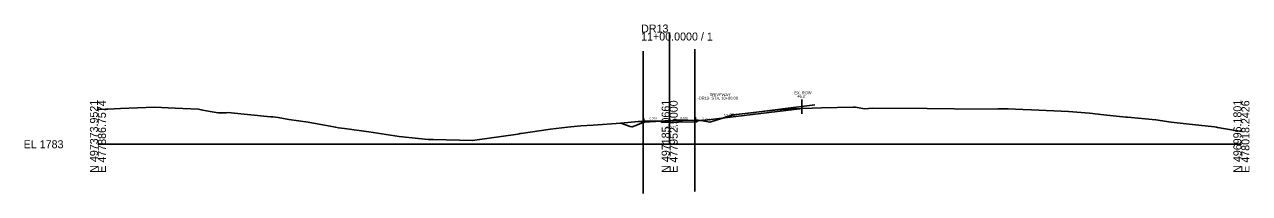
# Model space of a CAD drawing. Extents: x -26 to 403, y -10 to 2160.
# Drawn here: x -25.7 to 402.8, y 982.7 to 1042.1 of the extents above; entities that cross this region are included whole.
import ezdxf

# ---------------------------------------------------------------- set-up
doc = ezdxf.new("R2010")
doc.units = 0
for name, color, linetype in [('Exist Cross Section Cell', 7, 'Continuous'), ('Exist XS Center Line Elevation Label', 7, 'Continuous'), ('Exist XS Ground Line', 7, 'Continuous'), ('Pattern 3', 7, 'Continuous'), ('Prop XS Ditch Slope Text', 7, 'Continuous'), ('Prop XS Earthwork Shape', 7, 'Continuous'), ('Prop XS EOT Tick Mark', 7, 'Continuous'), ('Prop XS Finish Grade', 7, 'Continuous'), ('Prop XS Finish Grade Earthwork', 7, 'Continuous'), ('Prop XS Finish Grade Pavement', 7, 'Continuous'), ('Prop XS Pvmt Edge Slope', 7, 'Continuous'), ('Prop XS SE Text', 7, 'Continuous'), ('Prop XS Shoulder Borrow Shape', 7, 'Continuous'), ('Prop XS Subgrade Earthwork', 7, 'Continuous'), ('Scratch_Level_1', 7, 'Continuous'), ('Scratch_Level_4', 7, 'Continuous'), ('Scratch_Level_5', 7, 'Continuous'), ('Scratch_Level_6', 7, 'Continuous')]:
    doc.layers.add(name, color=color, linetype=linetype)

msp = doc.modelspace()

# ---------------------------------------------------------------- linework, layer by layer
at = {"layer": 'Exist Cross Section Cell'}
for p, q in [((200, 1000), (200, 1039.21)), ((0, 1000), (200, 1000)), ((200, 1000), (400, 1000))]:
    msp.add_line(p, q, dxfattribs=at)
at = {"layer": 'Exist XS Ground Line'}
msp.add_lwpolyline([(0, 1012.22), (2.69, 1012.35), (3.42, 1012.37), (7.84, 1012.53), (19.84, 1012.97), (27.02, 1012.64), (35.13, 1012.29), (36.66, 1011.95), (39.2, 1011.5), (42.1, 1010.99), (42.46, 1011), (42.89, 1011.02), (43.28, 1011.03), (43.98, 1011.05), (44.3, 1011.06), (44.83, 1011.08), (45.44, 1011.09), (60.37, 1009.6), (61.15, 1009.6), (63, 1009.4), (66.82, 1008.73), (73.59, 1007.75), (83.06, 1005.98), (84.18, 1005.79), (86.28, 1005.48), (94.77, 1004.34), (99.3, 1003.63), (105.36, 1002.75), (115.55, 1001.69), (115.95, 1001.65), (117.25, 1001.63), (131.07, 1001.37), (146.9, 1003.6), (147.39, 1003.67), (147.72, 1003.72), (148.04, 1003.76), (158.31, 1005.24), (164.28, 1005.97), (168.9, 1006.42), (173.26, 1006.73), (182.88, 1007.41), (186.23, 1006.29), (186.84, 1006.07), (187.76, 1006.46), (189.89, 1007.33), (190.76, 1007.69), (191.98, 1007.87), (192.39, 1007.89), (194.62, 1008.02), (196.46, 1008.08), (197.27, 1008.11), (198.27, 1008.17), (198.77, 1008.2), (199.97, 1008.27), (200.75, 1008.31), (202.53, 1008.41), (204.54, 1008.41), (205.16, 1008.42), (205.46, 1008.42), (206.35, 1008.4), (207.91, 1008.39), (208.77, 1008.42), (209.78, 1008.37), (211.18, 1008.29), (214.04, 1007.76), (214.71, 1007.94), (222.47, 1010.31), (233.3, 1011.64), (235.85, 1011.88), (237.77, 1012.1), (238.3, 1012.18), (238.64, 1012.18), (239.23, 1012.23), (240.04, 1012.26), (240.98, 1012.29), (243.16, 1012.39), (253.17, 1012.8), (264.23, 1013.06), (264.97, 1013.07), (268.16, 1012.39), (270.95, 1012.61), (290.05, 1012.59), (299.48, 1012.38), (300.58, 1012.32), (314.77, 1012.41), (318.45, 1012.39), (323.55, 1012.24), (326.56, 1012.12), (339.56, 1011.51), (346.91, 1010.88), (351.83, 1010.38), (359.53, 1009.52), (360.12, 1009.46), (370.12, 1008.58), (375.46, 1007.79), (380.71, 1007.14), (390.55, 1006.07), (391.3, 1005.97), (391.7, 1005.92), (400, 1004.46)], dxfattribs=at)
at = {"layer": 'Pattern 3'}
for p, q in [((246.18, 1015.66), (246.18, 1010.69)), ((211.5, 1008.35), (246.42, 1012.54)), ((209, 1008.45), (211.5, 1008.35))]:
    msp.add_line(p, q, dxfattribs=at)
at = {"layer": 'Prop XS Earthwork Shape'}
for points in [[(189, 1007.93), (182.88, 1007.41), (186.23, 1006.29), (186.84, 1006.07), (187.76, 1006.46), (189.89, 1007.33), (190.43, 1007.56), (189.98, 1008.01)], [(190.43, 1007.56), (190.76, 1007.69), (191, 1007.73), (191, 1007.55), (190.45, 1007.54)], [(197.2, 1008.11), (197.27, 1008.11), (198.27, 1008.17), (198.77, 1008.2), (199.97, 1008.27), (200.75, 1008.31), (202.53, 1008.41), (204.54, 1008.41), (205.16, 1008.42), (205.46, 1008.42), (206.35, 1008.4), (207.91, 1008.39), (208.77, 1008.42), (209.78, 1008.37), (209.96, 1008.36), (209.53, 1007.92), (209, 1007.91), (197.2, 1007.68)], [(209.96, 1008.36), (211.18, 1008.29), (214.04, 1007.76), (214.11, 1007.78), (211, 1008.37), (210.02, 1008.41)]]:
    msp.add_lwpolyline(points, close=True, dxfattribs=at)
at = {"layer": 'Prop XS EOT Tick Mark'}
for p, q in [((191, 1008.09), (191, 1009.09)), ((209, 1008.45), (209, 1009.45))]:
    msp.add_line(p, q, dxfattribs=at)
at = {"layer": 'Prop XS Finish Grade'}
for p, q in [((191, 1008.09), (189.98, 1008.01)), ((209, 1008.45), (210.02, 1008.41))]:
    msp.add_line(p, q, dxfattribs=at)
at = {"layer": 'Prop XS Finish Grade Earthwork'}
for p, q in [((189, 1007.93), (182.88, 1007.41)), ((189.98, 1008.01), (189, 1007.93)), ((210.02, 1008.41), (211, 1008.37)), ((211, 1008.37), (214.11, 1007.78))]:
    msp.add_line(p, q, dxfattribs=at)
at = {"layer": 'Prop XS Finish Grade Pavement'}
for p, q in [((191, 1008.09), (200, 1008.27)), ((200, 1008.27), (209, 1008.45))]:
    msp.add_line(p, q, dxfattribs=at)
at = {"layer": 'Prop XS Pvmt Edge Slope'}
for p, q in [((191, 1008.09), (190.45, 1007.54)), ((209, 1008.45), (209.53, 1007.92))]:
    msp.add_line(p, q, dxfattribs=at)
at = {"layer": 'Prop XS Shoulder Borrow Shape'}
for points in [[(191, 1008.09), (189.98, 1008.01), (190.45, 1007.54)], [(209, 1008.45), (210.02, 1008.41), (209.53, 1007.92)]]:
    msp.add_lwpolyline(points, close=True, dxfattribs=at)
at = {"layer": 'Prop XS Subgrade Earthwork'}
for p, q in [((190.45, 1007.54), (189.98, 1008.01)), ((191, 1007.55), (190.45, 1007.54)), ((191, 1007.55), (191, 1007.73)), ((197.2, 1007.68), (197.2, 1008.11)), ((197.2, 1007.68), (209, 1007.91)), ((209, 1007.91), (209.53, 1007.92)), ((209.53, 1007.92), (210.02, 1008.41))]:
    msp.add_line(p, q, dxfattribs=at)
at = {"layer": 'Scratch_Level_1'}
for p, q in [((208.77, 1033.42), (208.77, 983.42)), ((190.76, 1032.69), (190.76, 982.69))]:
    msp.add_line(p, q, dxfattribs=at)
at = {"layer": 'Scratch_Level_4'}
for p, q in [((250.83, 1013.8), (227.56, 1010.93)), ((214.04, 1007.76), (222.15, 1010.27)), ((222.15, 1010.27), (229.7, 1011.2))]:
    msp.add_line(p, q, dxfattribs=at)
at = {"layer": 'Scratch_Level_5'}
msp.add_lwpolyline([(42.1, 1010.99), (45.44, 1011.09), (60.37, 1009.6), (61.15, 1009.6), (63, 1009.4), (66.82, 1008.73), (73.59, 1007.75), (83.06, 1005.98), (84.18, 1005.79), (86.28, 1005.48), (94.77, 1004.34), (99.3, 1003.63), (105.36, 1002.75), (115.55, 1001.69), (115.95, 1001.65), (117.25, 1001.63), (131.07, 1001.37), (146.9, 1003.6), (147.39, 1003.67), (147.72, 1003.72), (148.04, 1003.76), (158.31, 1005.24), (164.28, 1005.97), (168.9, 1006.42), (173.26, 1006.73), (182.88, 1007.41), (186.23, 1006.29), (186.84, 1006.07), (187.76, 1006.46), (189.89, 1007.33), (190.76, 1007.69), (191.98, 1007.87), (192.39, 1007.89), (194.62, 1008.02), (196.46, 1008.08), (197.2, 1008.11)], dxfattribs=at)
at = {"layer": 'Scratch_Level_6'}
msp.add_line((197.2, 1008.11), (191, 1007.73), dxfattribs=at)

# ---------------------------------------------------------------- texts
at = {"layer": 'Exist Cross Section Cell'}
for s, p in [('DR13', (190, 1039.21)), ('11+00.0000 / 1', (190, 1036.41)), ('EL 1783', (-26, 998.6))]:
    msp.add_text(s, height=2.8, dxfattribs=at).set_placement(p)
for s, p in [('N 497373.9521', (0, 990)), ('E 477886.7574', (2.8, 990)), ('N 497185.0661', (200, 990)), ('E 477952.5000', (202.8, 990)), ('N 496996.1801', (400, 990)), ('E 478018.2426', (402.8, 990))]:
    msp.add_text(s, height=2.8, rotation=90, dxfattribs=at).set_placement(p)
at = {"layer": 'Exist XS Center Line Elevation Label'}
msp.add_text('1791.27', height=0.75, dxfattribs=at).set_placement((198.45, 1005.52))
at = {"layer": 'Pattern 3'}
for s, p in [('-DR13- STA. 10+80.00', (209.78, 1015.68)), ('DRIVEWAY', (213.96, 1016.88)), ('EX. ROW', (243.64, 1017.54)), ("46.2'", (244.68, 1016.34))]:
    msp.add_text(s, height=1, dxfattribs=at).set_placement(p)
msp.add_text('12.0%', height=1, rotation=6.413, dxfattribs=at).set_placement((219.01, 1009.54))
at = {"layer": 'Prop XS Ditch Slope Text'}
msp.add_text('5.23:1', height=0.75, rotation=349.1856, dxfattribs=at).set_placement((211.35, 1008.72))
at = {"layer": 'Prop XS SE Text'}
for p in [(192.99, 1008.66), (203.8, 1008.8)]:
    msp.add_text('0.020', height=0.75, rotation=1.1458, dxfattribs=at).set_placement(p)

doc.saveas('drawing.dxf')
